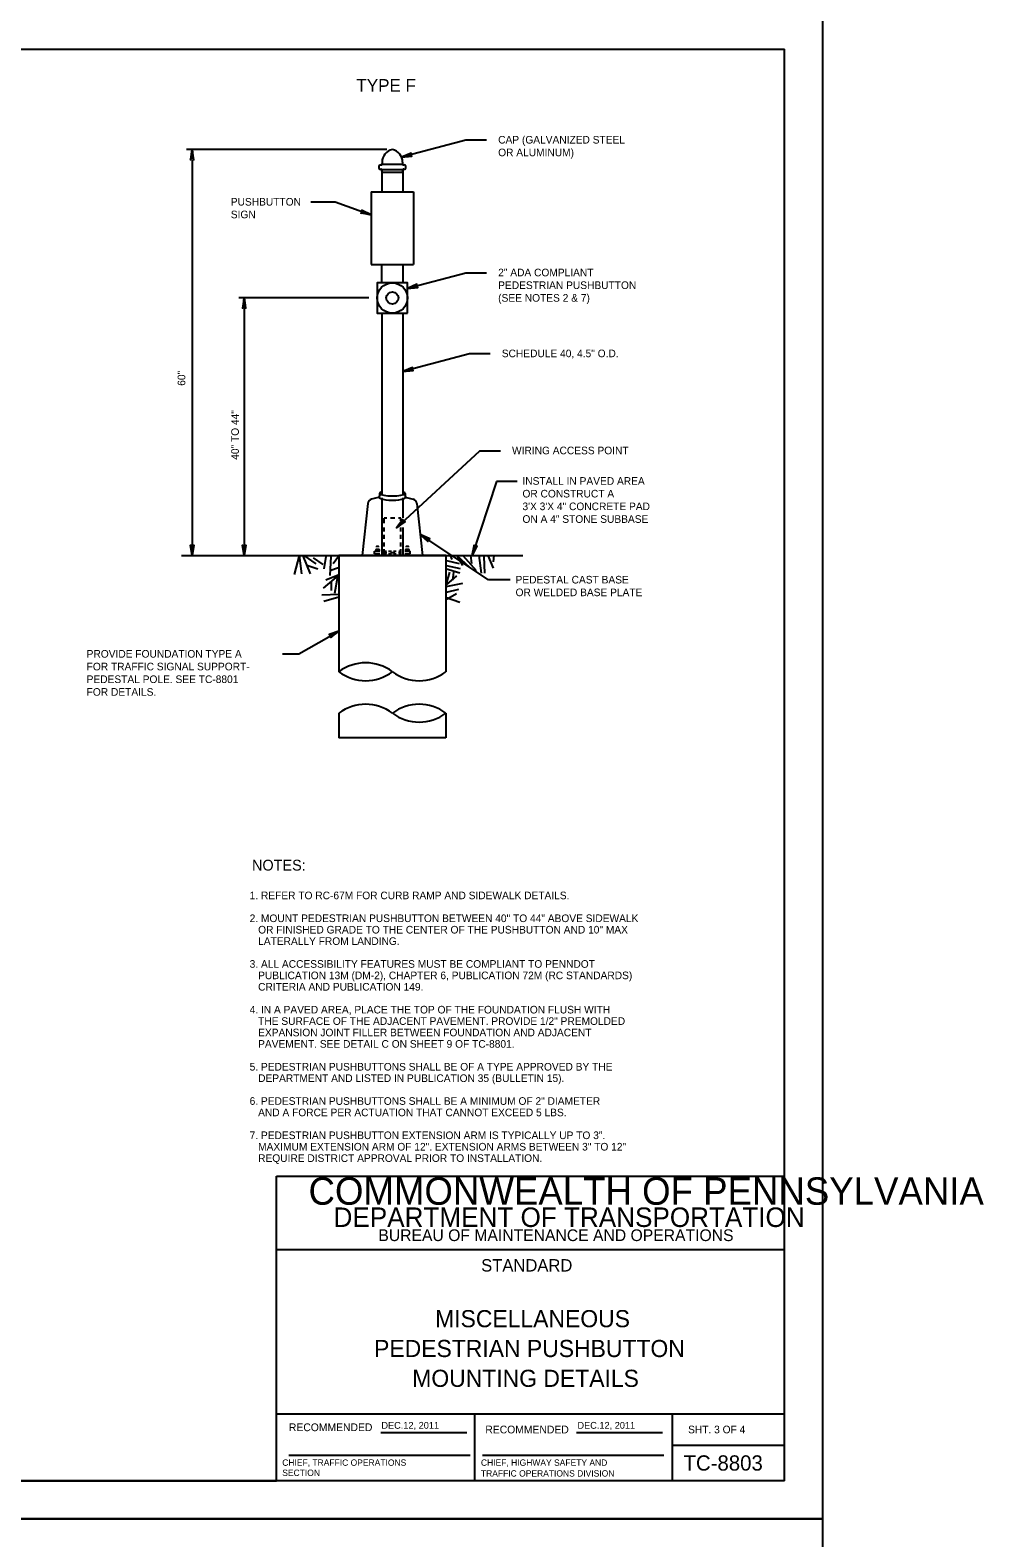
# Model space of a CAD drawing. Extents: x 36 to 940, y -1166 to 1210.
# Drawn here: x 565 to 940, y -579 to 15 of the extents above; entities that cross this region are included whole.
import ezdxf

# ---------------------------------------------------------------- set-up
doc = ezdxf.new("R2010")
doc.units = 0
for name, color, linetype in [('1', 7, 'Continuous'), ('2', 7, 'Continuous'), ('4', 7, 'Continuous'), ('Default', 7, 'Continuous'), ('Detail', 7, 'Continuous'), ('PLT-BNDY', 7, 'Continuous')]:
    doc.layers.add(name, color=color, linetype=linetype)

msp = doc.modelspace()

# ---------------------------------------------------------------- linework, layer by layer
at = {"layer": '1'}
for p, q in [((75.86, 7.17), (861.86, 7.17)), ((861.86, -556.83), (861.86, 7.17)), ((736.37, -28.72), (711.11, -35.39)), ((744.58, -28.72), (736.37, -28.72)), ((675.4, -52.97), (684.91, -52.97)), ((684.91, -52.97), (699.1, -58.09)), ((736.37, -81.02), (713.43, -87.09)), ((744.58, -81.02), (736.37, -81.02)), ((737.79, -112.9), (711.63, -119.81)), ((746, -112.9), (737.79, -112.9)), ((741.83, -151.14), (709.11, -181.37)), ((750.03, -151.14), (741.83, -151.14)), ((748.45, -163.16), (738.96, -192.24)), ((756.65, -163.16), (748.45, -163.16)), ((745.31, -201.94), (718.45, -184.03)), ((670.73, -192.24), (668.79, -199.82)), ((670.75, -192.32), (671.64, -199.48)), ((672.19, -192.5), (675.04, -199.48)), ((672.54, -192.32), (677.37, -195.53)), ((676.3, -193.21), (680.06, -195.9)), ((681.23, -192.68), (680.52, -197.5)), ((683.21, -192.68), (682.85, -200.19)), ((686.25, -192.68), (684.1, -195.53)), ((728.55, -192.24), (686.44, -192.24)), ((686.44, -192.24), (686.44, -238.1)), ((700.48, -191.65), (700.48, -190.62)), ((700.48, -191.65), (700.48, -190.62)), ((700.48, -190.62), (702.5, -190.62)), ((700.48, -191.65), (702.5, -191.65)), ((701.36, -192.18), (701.36, -191.65)), ((701.94, -191.65), (701.94, -192.18)), ((703.89, -190.62), (705.12, -190.62)), ((703.9, -191.65), (705.13, -191.65)), ((705.99, -190.63), (707.08, -190.63)), ((706, -191.65), (707.08, -191.65)), ((707.95, -191.65), (709.02, -191.65)), ((707.96, -190.63), (709.03, -190.63)), ((710, -190.63), (711.02, -190.63)), ((710, -191.65), (711.03, -191.65)), ((712.33, -190.62), (714.51, -190.62)), ((712.33, -191.65), (714.51, -191.65)), ((713.05, -192.24), (713.05, -191.65)), ((713.63, -191.65), (713.63, -192.24)), ((714.51, -191.65), (714.51, -190.62)), ((714.51, -191.65), (714.51, -190.62)), ((728.55, -192.24), (728.55, -238.1)), ((728.55, -192.24), (758.87, -192.24)), ((728.79, -194.27), (733.8, -195.52)), ((730.27, -192.24), (730.95, -193.92)), ((732.91, -192.31), (735.06, -196.25)), ((732.91, -192.31), (737.91, -196.96)), ((735.16, -192.24), (740.42, -198.21)), ((738.27, -192.31), (738.62, -195.52)), ((741.49, -192.31), (742.38, -199.28)), ((743.45, -192.67), (743.81, -199.28)), ((745.07, -192.31), (747.21, -197.32)), ((747.38, -192.31), (747.21, -194.82)), ((673.79, -196.08), (678.08, -197.5)), ((686.07, -200.19), (680.16, -205.18)), ((686.07, -200.01), (681.23, -201.97)), ((686.25, -197.15), (682.85, -198.4)), ((685.89, -200.71), (684.63, -207.33)), ((728.44, -197.49), (733.98, -199.1)), ((728.62, -196.25), (734.17, -197.49)), ((728.62, -203.92), (730.04, -198.92)), ((728.79, -203.92), (732.91, -200.36)), ((731.3, -201.96), (731.66, -198.92)), ((753.8, -201.94), (745.31, -201.94)), ((686.43, -207.69), (679.63, -207.87)), ((683.38, -202.51), (683.38, -206.07)), ((728.44, -209.82), (732.73, -207.32)), ((728.62, -204.46), (735.24, -203.21)), ((728.79, -206.79), (733.62, -205.54)), ((686.43, -208.76), (680.52, -210.38)), ((728.44, -208.75), (733.98, -210.71)), ((670.68, -231.06), (686.44, -222.08)), ((664.17, -231.06), (670.68, -231.06)), ((686.44, -254.41), (686.44, -264.15)), ((728.55, -254.41), (728.55, -264.15)), ((728.55, -264.15), (686.44, -264.15)), ((661.86, -556.83), (661.86, -436.83)), ((661.86, -436.83), (861.86, -436.83)), ((861.86, -465.83), (661.86, -465.83)), ((661.86, -530.45), (861.86, -530.45)), ((739.86, -530.45), (739.86, -556.83)), ((817.73, -556.83), (817.73, -530.45)), ((702.9, -537.8), (736.82, -537.8)), ((779.99, -537.8), (813.91, -537.8)), ((817.73, -542.83), (861.86, -542.83)), ((666.74, -546.79), (738.07, -546.79)), ((742.95, -546.79), (814.41, -546.79)), ((861.86, -556.83), (75.86, -556.83)), ((75.86, -556.83), (661.86, -556.83))]:
    msp.add_line(p, q, dxfattribs=at)
for points in [[(629.06, -36.18), (628.78, -36.03), (628.58, -32.35), (629.06, -36.18), (629.23, -36.37), (628.58, -32.35), (628.4, -36.03), (628.12, -36.16), (628.58, -32.35), (627.94, -36.37), (628.12, -36.16)], [(714.7, -33.98), (714.63, -34.28), (711.11, -35.39), (714.7, -33.98), (714.85, -33.77), (711.11, -35.39), (714.72, -34.66), (714.92, -34.89), (711.11, -35.39), (715.17, -35.02), (714.92, -34.89)], [(695.63, -56.41), (695.68, -56.72), (699.1, -58.09), (695.63, -56.41), (695.5, -56.19), (699.1, -58.09), (695.56, -57.09), (695.34, -57.31), (699.1, -58.09), (695.09, -57.41), (695.34, -57.31)], [(717.01, -85.67), (716.94, -85.98), (713.43, -87.09), (717.01, -85.67), (717.16, -85.46), (713.43, -87.09), (717.04, -86.35), (717.23, -86.58), (713.43, -87.09), (717.48, -86.71), (717.23, -86.58)], [(649.62, -94.68), (649.34, -94.53), (649.14, -90.85), (649.62, -94.68), (649.79, -94.87), (649.14, -90.85), (648.95, -94.53), (648.68, -94.66), (649.14, -90.85), (648.5, -94.87), (648.68, -94.66)], [(715.21, -118.4), (715.14, -118.7), (711.63, -119.81), (715.21, -118.4), (715.36, -118.19), (711.63, -119.81), (715.23, -119.08), (715.43, -119.31), (711.63, -119.81), (715.68, -119.44), (715.43, -119.31)], [(711.59, -178.41), (711.67, -178.71), (709.11, -181.37), (711.59, -178.41), (711.61, -178.16), (709.11, -181.37), (711.93, -179), (712.21, -179.1), (709.11, -181.37), (712.49, -179.1), (712.21, -179.1)], [(721.92, -185.71), (721.65, -185.87), (718.45, -184.03), (721.92, -185.71), (722.17, -185.68), (718.45, -184.03), (721.43, -186.19), (721.4, -186.49), (718.45, -184.03), (721.47, -186.76), (721.4, -186.49)], [(629.06, -188.41), (628.78, -188.56), (628.58, -192.24), (629.06, -188.41), (629.23, -188.22), (628.58, -192.24), (628.4, -188.56), (628.12, -188.42), (628.58, -192.24), (627.94, -188.22), (628.12, -188.42)], [(649.62, -188.41), (649.34, -188.56), (649.14, -192.24), (649.62, -188.41), (649.79, -188.22), (649.14, -192.24), (648.95, -188.56), (648.68, -188.42), (649.14, -192.24), (648.5, -188.22), (648.68, -188.42)], [(701.36, -189), (701.36, -188.57), (701.94, -188.57), (701.94, -189)], [(701.36, -189.98), (701.36, -189.57)], [(701.94, -189.57), (701.94, -189.98)], [(713.05, -189), (713.05, -188.57), (713.63, -188.57), (713.63, -189)], [(713.05, -189.98), (713.05, -189.57)], [(713.63, -189.57), (713.63, -189.98)], [(739.72, -188.46), (739.94, -188.68), (738.96, -192.24), (739.72, -188.46), (739.63, -188.22), (738.96, -192.24), (740.3, -188.81), (740.61, -188.77), (738.96, -192.24), (740.85, -188.63), (740.61, -188.77)], [(683.34, -224.37), (683.33, -224.06), (686.44, -222.08), (683.34, -224.37), (683.25, -224.61), (686.44, -222.08), (683.14, -223.72), (682.89, -223.55), (686.44, -222.08), (682.62, -223.49), (682.89, -223.55)]]:
    msp.add_lwpolyline(points, dxfattribs=at)
for points in [[(701.06, -190.62), (701.06, -189.98), (702.23, -189.98), (702.23, -190.62)], [(712.75, -190.62), (712.75, -189.98), (713.92, -189.98), (713.92, -190.62)]]:
    msp.add_lwpolyline(points, close=True, dxfattribs=at)
for centre, start, end in [((696.96, -252.06), 52.97243, 127.02757), ((696.96, -224.14), 232.97243, 307.02757), ((718.02, -224.14), 232.97243, 307.02757), ((696.96, -268.37), 52.97243, 127.02757), ((718.02, -268.37), 52.97243, 127.02757), ((718.02, -240.46), 232.97243, 307.02757)]:
    msp.add_arc(centre, 17.48, start, end, dxfattribs=at)
at = {"layer": 'Default'}
for p, q in [((705.35, -32.35), (626.43, -32.35)), ((628.58, -36.59), (628.58, -192.24)), ((702.92, -38.44), (702.98, -38.44)), ((703.08, -40.13), (702.92, -40.13)), ((703.29, -40.17), (703.29, -49)), ((703.29, -40.88), (703.29, -40.33)), ((703.4, -37.31), (703.4, -38.05)), ((703.71, -41.28), (711.21, -41.28)), ((711.52, -37.31), (711.52, -38.05)), ((711.63, -40.17), (711.63, -49)), ((711.63, -40.88), (711.63, -40.33)), ((711.99, -40.13), (711.83, -40.13)), ((711.93, -38.44), (711.99, -38.44)), ((712.83, -39.34), (712.83, -39.24)), ((699.1, -49), (715.81, -49)), ((699.1, -49), (699.1, -77.65)), ((715.81, -49), (715.81, -77.65)), ((699.1, -77.65), (715.81, -77.65)), ((703.29, -84.88), (703.29, -77.65)), ((711.63, -77.65), (711.63, -84.88)), ((698.26, -90.85), (646.99, -90.85)), ((649.14, -90.85), (649.14, -192.24)), ((701.49, -96.82), (713.43, -96.82)), ((703.29, -96.82), (703.29, -168.42)), ((711.63, -96.82), (711.63, -168.42)), ((697.87, -171.85), (695.56, -192.24)), ((701.9, -169.51), (699.25, -170.16)), ((702.4, -167.85), (702.4, -168.9)), ((703.29, -169.55), (703.29, -192.24)), ((711.63, -169.55), (711.63, -177.4)), ((712.51, -167.85), (712.51, -168.9)), ((713.01, -169.51), (715.66, -170.16)), ((717.04, -171.85), (719.35, -192.24)), ((711.63, -181.32), (711.63, -192.24)), ((624.44, -192.24), (757.44, -192.24))]:
    msp.add_line(p, q, dxfattribs=at)
msp.add_lwpolyline([(713.43, -96.82), (713.43, -84.88), (701.49, -84.88), (701.49, -96.82), (701.49, -96.82)], dxfattribs=at)
for radius in [5.97, 2.39]:
    msp.add_circle((707.46, -90.85), radius, dxfattribs=at)
for centre, major_axis, ratio, start_param, end_param in [((708.83, -37.35), (5.43, 0), 0.952381, 1.825494, 3.132766), ((706.09, -37.35), (5.43, 0), 0.952381, 0.008827, 1.316099), ((702.92, -39.24), (0.833, 0), 0.952381, 1.570796, 3.141593), ((702.92, -39.34), (0.833, 0), 0.952381, 3.141593, 4.712389), ((702.98, -38.05), (0.417, 0), 0.952381, 4.712389, 6.283185), ((703.08, -40.33), (0.208, 0), 0.952381, 0, 1.570796), ((707.54, -40.13), (-4.46, 0), 0.026054, 0.212556, 2.780907), ((703.71, -40.88), (0.417, 0), 0.952381, 3.141593, 4.712389), ((707.46, -38.05), (-4.06, 0), 0.012269, 0, 3.141593), ((711.21, -40.88), (0.417, 0), 0.952381, 4.712389, 6.283185), ((711.93, -38.05), (0.417, 0), 0.952381, 3.141593, 4.712389), ((711.83, -40.33), (0.208, 0), 0.952381, 1.570796, 3.141593), ((711.99, -39.24), (0.833, 0), 0.952381, 0, 1.570796), ((711.99, -39.34), (0.833, 0), 0.952381, 4.712389, 6.283185), ((699.7, -171.85), (1.83, 0), 0.952381, 1.821847, 3.141593), ((707.46, -167.85), (-5.06, 0), 0.197066, 5.681211, 10.026837), ((701.73, -168.9), (0.667, 0), 0.952381, 4.96344, 6.283185), ((707.46, -169.29), (-5.2, 0), 0.23546, 6.283185, 9.424778), ((713.18, -168.9), (0.667, 0), 0.952381, 3.141593, 4.461338), ((715.21, -171.85), (1.83, 0), 0.952381, 0, 1.319746)]:
    msp.add_ellipse(centre, major_axis=major_axis, ratio=ratio, start_param=start_param, end_param=end_param, dxfattribs=at)
at = {"layer": 'Detail'}
for p, q in [((705.3, -177.62), (704.18, -177.62)), ((704.18, -179.54), (704.18, -177.62)), ((710.8, -177.62), (709.86, -177.62)), ((710.8, -178.69), (710.8, -177.62)), ((704.18, -191.19), (704.18, -189.76)), ((710.8, -191.19), (710.8, -189.76)), ((705.3, -191.19), (704.18, -191.19)), ((710.8, -191.19), (709.86, -191.19))]:
    msp.add_line(p, q, dxfattribs=at)
for points in [[(708.49, -177.62), (706.77, -177.62)], [(704.18, -182.82), (704.18, -181.23)], [(710.8, -182.82), (710.8, -181.23)], [(704.18, -185.79), (704.18, -184.2)], [(704.18, -188.79), (704.18, -187.19)], [(710.8, -185.79), (710.8, -184.2)], [(710.8, -188.79), (710.8, -187.19)], [(708.49, -191.19), (706.77, -191.19)]]:
    msp.add_lwpolyline(points, dxfattribs=at)
at = {"layer": 'PLT-BNDY'}
for points in [[(35.86, 22.17), (876.86, 22.17), (876.86, -571.83), (35.86, -571.83)], [(35.86, -571.83), (876.86, -571.83), (876.86, -1165.83), (35.86, -1165.83)]]:
    msp.add_lwpolyline(points, close=True, dxfattribs=at)

# ---------------------------------------------------------------- texts
at = {"layer": '1'}
for s, height, p in [('COMMONWEALTH OF PENNSYLVANIA', 10.7828, (674.45, -448.1)), ('DEPARTMENT OF TRANSPORTATION', 7.6837, (684.31, -456.85)), ('BUREAU OF MAINTENANCE AND OPERATIONS', 4.6253, (701.95, -462.41)), ('MISCELLANEOUS', 6.75, (724.3, -496.35)), ('PEDESTRIAN PUSHBUTTON', 6.75, (700.28, -508.1)), ('MOUNTING DETAILS', 6.75, (715.3, -519.85)), ('RECOMMENDED', 3.0516, (666.73, -537.3)), ('RECOMMENDED', 3.0516, (744.08, -538.18)), ('SHT. 3 OF 4', 3, (823.94, -538.14)), ('TC-8803', 6, (822.14, -552.83))]:
    msp.add_text(s, height=height, dxfattribs=at).set_placement(p)
at = {"layer": '2'}
for s, height, p in [('TYPE F', 5, (693.32, -9.61)), ('CAP (GALVANIZED STEEL', 3, (749.14, -30.01)), ('OR ALUMINUM)', 3, (749.14, -35.01)), ('PUSHBUTTON', 3, (643.84, -54.44)), ('SIGN', 3, (643.84, -59.44)), ('2" ADA COMPLIANT', 3, (749.14, -82.31)), ('PEDESTRIAN PUSHBUTTON', 3, (749.14, -87.31)), ('(SEE NOTES 2 & 7)', 3, (749.14, -92.31)), ('SCHEDULE 40, 4.5" O.D.', 3, (750.56, -114.19)), ('WIRING ACCESS POINT', 3, (754.59, -152.43)), ('INSTALL IN PAVED AREA  ', 3, (758.7, -164.44)), ('3\'X 3\'X 4" CONCRETE PAD ', 3, (758.7, -174.44)), ('OR CONSTRUCT A ', 3, (758.7, -169.44)), ('ON A 4" STONE SUBBASE', 3, (758.7, -179.44)), ('PEDESTAL CAST BASE', 3, (755.99, -203.33)), ('OR WELDED BASE PLATE', 3, (755.99, -208.33)), ('PROVIDE FOUNDATION TYPE A', 3, (587.07, -232.55)), ('FOR TRAFFIC SIGNAL SUPPORT- ', 3, (587.07, -237.55)), ('PEDESTAL POLE. SEE TC-8801 ', 3, (587.07, -242.55)), ('FOR DETAILS.', 3, (587.07, -247.55)), ('NOTES:', 4.25, (652.19, -316.43)), ('1. REFER TO RC-67M FOR CURB RAMP AND SIDEWALK DETAILS.', 3, (651.26, -327.73)), ('2. MOUNT PEDESTRIAN PUSHBUTTON BETWEEN 40" TO 44" ABOVE SIDEWALK ', 3, (651.26, -336.73)), ('   OR FINISHED GRADE TO THE CENTER OF THE PUSHBUTTON AND 10" MAX', 3, (651.26, -341.23)), ('   LATERALLY FROM LANDING.', 3, (651.26, -345.73)), ('3. ALL ACCESSIBILITY FEATURES MUST BE COMPLIANT TO PENNDOT ', 3, (651.26, -354.73)), ('   PUBLICATION 13M (DM-2), CHAPTER 6, PUBLICATION 72M (RC STANDARDS)', 3, (651.26, -359.23)), ('   CRITERIA AND PUBLICATION 149.', 3, (651.26, -363.73)), ('4. IN A PAVED AREA, PLACE THE TOP OF THE FOUNDATION FLUSH WITH', 3, (651.26, -372.73)), ('   THE SURFACE OF THE ADJACENT PAVEMENT. PROVIDE 1/2" PREMOLDED', 3, (651.26, -377.23)), ('   EXPANSION JOINT FILLER BETWEEN FOUNDATION AND ADJACENT ', 3, (651.26, -381.73)), ('   PAVEMENT. SEE DETAIL C ON SHEET 9 OF TC-8801.', 3, (651.26, -386.23)), ('5. PEDESTRIAN PUSHBUTTONS SHALL BE OF A TYPE APPROVED BY THE', 3, (651.26, -395.23)), ('   DEPARTMENT AND LISTED IN PUBLICATION 35 (BULLETIN 15).', 3, (651.26, -399.73)), ('6. PEDESTRIAN PUSHBUTTONS SHALL BE A MINIMUM OF 2" DIAMETER', 3, (651.26, -408.73)), ('   AND A FORCE PER ACTUATION THAT CANNOT EXCEED 5 LBS.', 3, (651.26, -413.23)), ('7. PEDESTRIAN PUSHBUTTON EXTENSION ARM IS TYPICALLY UP TO 3".', 3, (651.26, -422.23)), ('   MAXIMUM EXTENSION ARM OF 12". EXTENSION ARMS BETWEEN 3" TO 12"', 3, (651.26, -426.73)), ('   REQUIRE DISTRICT APPROVAL PRIOR TO INSTALLATION.', 3, (651.26, -431.23)), ('DEC.12, 2011', 2.7032, (703.15, -536.36))]:
    msp.add_text(s, height=height, dxfattribs=at).set_placement(p)
for s, height, rotation, p in [('  60"', 3, 90, (625.91, -127.67)), ('40" TO 44"', 3, 90, (647.02, -154.6)), ('DEC.12, 2011', 2.7032, 360, (780.37, -536.36))]:
    msp.add_text(s, height=height, rotation=rotation, dxfattribs=at).set_placement(p)
at = {"layer": '4'}
msp.add_text('STANDARD', height=4.881, rotation=360, dxfattribs=at).set_placement((742.45, -474.41))
at = {"layer": 'Default'}
for s, p in [('SECTION', (664.1, -554.94)), ('CHIEF, TRAFFIC OPERATIONS', (664.1, -550.94)), ('CHIEF, HIGHWAY SAFETY AND', (742.35, -550.94)), ('TRAFFIC OPERATIONS DIVISION', (742.35, -555.19))]:
    msp.add_text(s, height=2.5, dxfattribs=at).set_placement(p)

doc.saveas('drawing.dxf')
